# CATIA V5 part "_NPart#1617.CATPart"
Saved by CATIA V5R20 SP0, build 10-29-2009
Part number: 3IMAN8x3-80º
Revision: ANY
Definition: UNKNOWN
Nomenclature: 3IMAN8x3-80º
Source: Unknown
Bounding box of the stored display mesh (mm): x -4 to 4, y -3.804 to 3.804, z 0 to 3
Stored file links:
  C:\Users\Utente\Desktop\IO LAVORO\3D X SITO CF\CUMSA\3D files SX.256062\SX 256062\_NPart#1617.CATPart
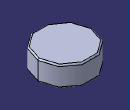
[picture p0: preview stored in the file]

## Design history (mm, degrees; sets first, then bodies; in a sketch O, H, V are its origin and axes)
Body1 "Redondeo1" (main body)
  Solid1: solid without history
